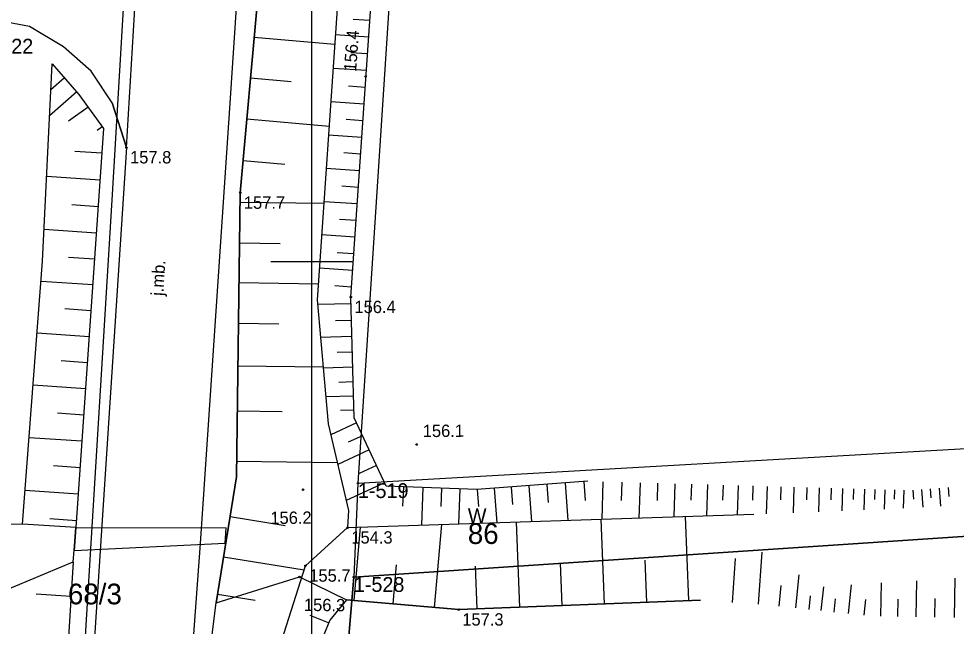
# Model space of a CAD drawing. Extents: x 5598798 to 5599616, y 5661498 to 5662453.
# Drawn here: x 5599182.2 to 5599239.2, y 5661877.8 to 5661914.8 of the extents above; entities that cross this region are included whole.
import ezdxf

# ---------------------------------------------------------------- set-up
doc = ezdxf.new("R2010")
doc.units = 0
for name, color, linetype in [('BUBZ_L_1', 7, 'Continuous'), ('BUIB_L_4', 7, 'Continuous'), ('Dzialki', 7, 'Continuous'), ('Kontury', 7, 'Continuous'), ('KTJZ_E_T_0', 7, 'Continuous'), ('KTJZ_L_0', 7, 'Continuous'), ('KTKR_L_0', 7, 'Continuous'), ('Numery_dzialek', 7, 'Continuous'), ('Numery_punktow', 7, 'Continuous'), ('Numery_uzytkow', 7, 'Continuous'), ('Podzial_sekcyjny_krzyze', 7, 'Continuous'), ('Podzial_sekcyjny_podstawowy', 7, 'Continuous'), ('PTRW_L_0', 7, 'Continuous'), ('PTRW_L_1', 7, 'Continuous'), ('Punkty', 7, 'Continuous'), ('RTPW_T_0', 7, 'Continuous'), ('SUPT_L_0', 7, 'Continuous'), ('Uzytki', 7, 'Continuous')]:
    doc.layers.add(name, color=color, linetype=linetype)

# ---------------------------------------------------------------- blocks, each defined once
blk = doc.blocks.new('GRO')
blk.add_circle((0, 0), 0.045)
blk = doc.blocks.new('POINT_DISPLAY')
blk.add_line((0, 0), (0, 0))
blk = doc.blocks.new('2_RTPW01')
blk.add_circle((0, 0), 0.045)

msp = doc.modelspace()

# ---------------------------------------------------------------- linework, layer by layer
at = {"layer": 'BUBZ_L_1'}
for p, q in [((5599195.64, 5661904.18), (5599197.66, 5661926.64)), ((5599201.55, 5661915.67), (5599200.33, 5661897.67)), ((5599202.37, 5661897.83), (5599203.6, 5661915.78)), ((5599203.522517, 5661914.649259), (5599202.506386, 5661914.718888)), ((5599196.491406, 5661913.646618), (5599201.383041, 5661913.206676)), ((5599203.452888, 5661913.633128), (5599201.42138, 5661913.772334)), ((5599203.383285, 5661912.617374), (5599202.367908, 5661912.686951)), ((5599183.618148, 5661900.022636), (5599184.202019, 5661912.021845)), ((5599184.202019, 5661912.021845), (5599185.830056, 5661910.15661)), ((5599203.313708, 5661911.601997), (5599201.283708, 5661911.7411)), ((5599184.951623, 5661911.163026), (5599184.125127, 5661910.441633)), ((5599196.268985, 5661911.173565), (5599198.742038, 5661910.951144)), ((5599185.701228, 5661910.304208), (5599184.048236, 5661908.861422)), ((5599185.830056, 5661910.15661), (5599187.322908, 5661908.083205)), ((5599203.244156, 5661910.586997), (5599202.229533, 5661910.656523)), ((5599203.174631, 5661909.572374), (5599201.146138, 5661909.711373)), ((5599186.381659, 5661909.390494), (5599185.185928, 5661908.529568)), ((5599196.044088, 5661908.672973), (5599201.045271, 5661908.223179)), ((5599203.105131, 5661908.558127), (5599202.091261, 5661908.627601)), ((5599187.322908, 5661908.083205), (5599185.646749, 5661883.824963)), ((5599187.242586, 5661908.194763), (5599186.933624, 5661907.97231)), ((5599203.035657, 5661907.544257), (5599201.008669, 5661907.683154)), ((5599187.219157, 5661906.581675), (5599185.58373, 5661906.694678)), ((5599195.816686, 5661906.144536), (5599198.345123, 5661905.917135)), ((5599202.966208, 5661906.530763), (5599201.953091, 5661906.600186)), ((5599202.896786, 5661905.517646), (5599200.871303, 5661905.65644)), ((5599187.106155, 5661904.946248), (5599183.868612, 5661905.16995)), ((5599202.827389, 5661904.504905), (5599201.815024, 5661904.574276)), ((5599195.41, 5661886.89), (5599195.64, 5661904.18)), ((5599186.994304, 5661903.327476), (5599185.392018, 5661903.438188)), ((5599195.632346, 5661903.604643), (5599200.727643, 5661903.536863)), ((5599202.758018, 5661903.492539), (5599200.734039, 5661903.63123)), ((5599202.688673, 5661902.48055), (5599201.677059, 5661902.549869)), ((5599186.883592, 5661901.725191), (5599183.711657, 5661901.94436)), ((5599202.619353, 5661901.468936), (5599200.596877, 5661901.607524)), ((5599195.599354, 5661901.124487), (5599198.07951, 5661901.091495)), ((5599202.55006, 5661900.457698), (5599201.539197, 5661900.526966)), ((5599182.39565, 5661884.02401), (5599183.618148, 5661900.022636)), ((5599186.774007, 5661900.139223), (5599185.204192, 5661900.247692)), ((5599202.480791, 5661899.446835), (5599200.459816, 5661899.58532)), ((5599186.665538, 5661898.569409), (5599183.523691, 5661898.786499)), ((5599195.567236, 5661898.710037), (5599200.396138, 5661898.6458)), ((5599202.411549, 5661898.436347), (5599201.401437, 5661898.505564)), ((5599200.33, 5661897.67), (5599201, 5661890.13)), ((5599202.57, 5661890.48), (5599202.37, 5661897.83)), ((5599186.556993, 5661896.998485), (5599184.980353, 5661897.107425)), ((5599202.381008, 5661897.425438), (5599200.356627, 5661897.370352)), ((5599202.408551, 5661896.413247), (5599201.427485, 5661896.386551)), ((5599195.534459, 5661896.24609), (5599197.998406, 5661896.213313)), ((5599186.448053, 5661895.421845), (5599183.283299, 5661895.640519)), ((5599202.435247, 5661895.43218), (5599200.53345, 5661895.380431)), ((5599202.461122, 5661894.481282), (5599201.539463, 5661894.456203)), ((5599186.338716, 5661893.839468), (5599184.750581, 5661893.949203)), ((5599195.499916, 5661893.649342), (5599200.693412, 5661893.580255)), ((5599202.486201, 5661893.559623), (5599200.699566, 5661893.511008)), ((5599186.228982, 5661892.251333), (5599183.041153, 5661892.471601)), ((5599202.510509, 5661892.666306), (5599201.644661, 5661892.642745)), ((5599202.534069, 5661891.800458), (5599200.855622, 5661891.754786)), ((5599186.118848, 5661890.657419), (5599184.519133, 5661890.767954)), ((5599195.463511, 5661890.912634), (5599198.200218, 5661890.876229)), ((5599202.556905, 5661890.961234), (5599201.743488, 5661890.939101)), ((5599202.710726, 5661890.178963), (5599201.156826, 5661889.452562)), ((5599204.51, 5661886.33), (5599202.57, 5661890.48)), ((5599201, 5661890.13), (5599202.22, 5661884.86)), ((5599186.008313, 5661889.057705), (5599182.797242, 5661889.279579)), ((5599203.073926, 5661889.402013), (5599202.214259, 5661889.000145)), ((5599203.475795, 5661888.542346), (5599201.573414, 5661887.65304)), ((5599185.897376, 5661887.45217), (5599184.285998, 5661887.56351)), ((5599195.422781, 5661887.850777), (5599201.546496, 5661887.769316)), ((5599203.920448, 5661887.591156), (5599202.86799, 5661887.099163)), ((5599194.18, 5661879.24), (5599195.41, 5661886.89)), ((5599204.41244, 5661886.538698), (5599202.083426, 5661885.449954)), ((5599210.04, 5661886.12), (5599204.51, 5661886.33)), ((5599205.564329, 5661886.289962), (5599205.519298, 5661885.104138)), ((5599206.750153, 5661886.244931), (5599206.66328, 5661883.957291)), ((5599207.893973, 5661886.201495), (5599207.852075, 5661885.098191)), ((5599208.997277, 5661886.159597), (5599208.91645, 5661884.03115)), ((5599216.78, 5661886.63), (5599210.04, 5661886.12)), ((5599211.085384, 5661886.199102), (5599211.243656, 5661884.107437)), ((5599212.131217, 5661886.278237), (5599212.212045, 5661885.210034)), ((5599213.199421, 5661886.359066), (5599213.364535, 5661884.17696)), ((5599214.290474, 5661886.441623), (5599214.374797, 5661885.327232)), ((5599215.404865, 5661886.525947), (5599215.577119, 5661884.249489)), ((5599216.543094, 5661886.612074), (5599216.631064, 5661885.449497)), ((5599217.707941, 5661886.603568), (5599217.642815, 5661884.317203)), ((5599218.851123, 5661886.571006), (5599218.819559, 5661885.462874)), ((5599219.959255, 5661886.539441), (5599219.898062, 5661884.39113)), ((5599221.033411, 5661886.508845), (5599221.003752, 5661885.467624)), ((5599222.074632, 5661886.479186), (5599222.017134, 5661884.460594)), ((5599223.083928, 5661886.450437), (5599223.05606, 5661885.472087)), ((5599224.062278, 5661886.42257), (5599224.008252, 5661884.525863)), ((5599225.010631, 5661886.395557), (5599224.984447, 5661885.476281)), ((5599225.929907, 5661886.369372), (5599225.879143, 5661884.587192)), ((5599226.820997, 5661886.34399), (5599226.796394, 5661885.480221)), ((5599227.684766, 5661886.319386), (5599227.637234, 5661884.650657)), ((5599228.51913, 5661886.29562), (5599228.496185, 5661885.490062)), ((5599229.324689, 5661886.272674), (5599229.280382, 5661884.717181)), ((5599230.102435, 5661886.250521), (5599230.081046, 5661885.499626)), ((5599230.85333, 5661886.229132), (5599230.812029, 5661884.779191)), ((5599231.5783, 5661886.208482), (5599231.558363, 5661885.508541)), ((5599232.278241, 5661886.188545), (5599232.239743, 5661884.836994)), ((5599232.954016, 5661886.169296), (5599232.935432, 5661885.516851)), ((5599233.606461, 5661886.150711), (5599233.570575, 5661884.890873)), ((5599237.615384, 5661886.162655), (5599237.658168, 5661885.619911)), ((5599238.158128, 5661886.20544), (5599238.244467, 5661885.110186)), ((5599238.705755, 5661886.248609), (5599238.749313, 5661885.696056)), ((5599185.786036, 5661885.840792), (5599182.551553, 5661886.064283)), ((5599210.061454, 5661886.121623), (5599210.138933, 5661885.097693)), ((5599234.23638, 5661886.132768), (5599234.219056, 5661885.524597)), ((5599234.844551, 5661886.115445), (5599234.8111, 5661884.941097)), ((5599235.431725, 5661886.09872), (5599235.415577, 5661885.531818)), ((5599235.998626, 5661886.082572), (5599235.967446, 5661884.987913)), ((5599236.545671, 5661886.07833), (5599236.587594, 5661885.546524)), ((5599237.077478, 5661886.120252), (5599237.162284, 5661885.04444)), ((5599195.023599, 5661884.486771), (5599198.375505, 5661883.947837)), ((5599202.22, 5661884.86), (5599202.17, 5661883.81)), ((5599202.17, 5661883.81), (5599226.88, 5661884.62)), ((5599222.921658, 5661879.372052), (5599222.719977, 5661884.483633)), ((5599185.646749, 5661883.824963), (5599182.39565, 5661884.02401)), ((5599185.67429, 5661884.22355), (5599184.051164, 5661884.335703)), ((5599207.462869, 5661878.946736), (5599207.899199, 5661883.997804)), ((5599212.647264, 5661878.966668), (5599212.44288, 5661884.146747)), ((5599217.801557, 5661879.170034), (5599217.598529, 5661884.315751)), ((5599199.61, 5661881.49), (5599202.17, 5661883.81)), ((5599202.562704, 5661879.37003), (5599202.948449, 5661883.835518)), ((5599227.169305, 5661879.151962), (5599227.39118, 5661882.317959)), ((5599181.124984, 5661879.908151), (5599185.479134, 5661881.732747)), ((5599185.479134, 5661881.732747), (5599182.923041, 5661841.717691)), ((5599194.629438, 5661882.035288), (5599199.532405, 5661881.246968)), ((5599215.228699, 5661879.06852), (5599215.126846, 5661881.649955)), ((5599220.365868, 5661879.271211), (5599220.264691, 5661881.835521)), ((5599225.586306, 5661879.2629), (5599225.772964, 5661881.926365)), ((5599198.02, 5661876.51), (5599199.61, 5661881.49)), ((5599204.937335, 5661879.164901), (5599205.142464, 5661881.539532)), ((5599210.057224, 5661878.864476), (5599209.954691, 5661881.463149)), ((5599229.434035, 5661878.92122), (5599229.645525, 5661880.945479)), ((5599234.601569, 5661878.428875), (5599234.641444, 5661880.441587)), ((5599236.748534, 5661878.38634), (5599236.79198, 5661880.579344)), ((5599239.087815, 5661878.339996), (5599239.135153, 5661880.72944)), ((5599228.421906, 5661879.026965), (5599228.552722, 5661880.279059)), ((5599230.980807, 5661878.759617), (5599231.133055, 5661880.21685)), ((5599232.646927, 5661878.585545), (5599232.828711, 5661880.325469)), ((5599185.344339, 5661879.622558), (5599183.234126, 5661879.757355)), ((5599194.262906, 5661879.755638), (5599196.542557, 5661879.389106)), ((5599202.1, 5661879.41), (5599201.09, 5661878.18)), ((5599208.93, 5661878.82), (5599202.1, 5661879.41)), ((5599223.63, 5661879.4), (5599208.93, 5661878.82)), ((5599230.25219, 5661878.835741), (5599230.337669, 5661879.653896)), ((5599231.776965, 5661878.676436), (5599231.860146, 5661879.472595)), ((5599233.597534, 5661878.486228), (5599233.696851, 5661879.436835)), ((5599235.652032, 5661878.408064), (5599235.672843, 5661879.458526)), ((5599237.893092, 5661878.363665), (5599237.915768, 5661879.508224)), ((5599192.07, 5661862.5), (5599194.18, 5661879.24)), ((5599201.09, 5661878.18), (5599199.56, 5661874.43)), ((5599201.020079, 5661878.008624), (5599199.904587, 5661878.463744))]:
    msp.add_line(p, q, dxfattribs=at)
at = {"layer": 'BUIB_L_4'}
for p, q in [((5599185.646749, 5661883.824963), (5599185.534757, 5661882.427047)), ((5599185.646749, 5661883.824963), (5599194.779859, 5661883.794812)), ((5599194.727097, 5661882.855368), (5599194.779859, 5661883.794812)), ((5599185.534757, 5661882.427047), (5599194.727097, 5661882.855368))]:
    msp.add_line(p, q, dxfattribs=at)
at = {"layer": 'Dzialki'}
for p, q in [((5599207.13, 5661952.92), (5599202.8, 5661886.51)), ((5599202.8, 5661886.51), (5599366.78, 5661895.9)), ((5599202.55, 5661880.8), (5599363.22, 5661891.49)), ((5599202.8, 5661886.51), (5599202.55, 5661880.8)), ((5599202.55, 5661880.8), (5599192.37, 5661761.69))]:
    msp.add_line(p, q, dxfattribs=at)
at = {"layer": 'Kontury'}
for p, q in [((5599207.13, 5661952.92), (5599202.8, 5661886.51)), ((5599202.55, 5661880.8), (5599363.22, 5661891.49)), ((5599202.8, 5661886.51), (5599202.55, 5661880.8)), ((5599192.37, 5661761.69), (5599202.55, 5661880.8))]:
    msp.add_line(p, q, dxfattribs=at)
at = {"layer": 'KTJZ_L_0'}
for p, q in [((5599196.72, 5661936.01), (5599194.99, 5661909.33)), ((5599195.64, 5661904.18), (5599197.66, 5661926.64)), ((5599188.72, 5661906.93), (5599189.38, 5661917.79)), ((5599182.82, 5661914.28), (5599180.59, 5661914.71)), ((5599184.89, 5661913.05), (5599182.82, 5661914.28)), ((5599186.58, 5661911.58), (5599184.89, 5661913.05)), ((5599187.86, 5661909.64), (5599186.58, 5661911.58)), ((5599187.86, 5661909.64), (5599188.72, 5661906.93)), ((5599194.99, 5661909.33), (5599193.21, 5661882.85)), ((5599188.72, 5661906.93), (5599185.78, 5661861.81)), ((5599195.41, 5661886.89), (5599195.64, 5661904.18)), ((5599194.18, 5661879.24), (5599195.41, 5661886.89)), ((5599193.21, 5661882.85), (5599191.03, 5661853.22)), ((5599192.07, 5661862.5), (5599194.18, 5661879.24))]:
    msp.add_line(p, q, dxfattribs=at)
at = {"layer": 'KTKR_L_0'}
for p, q in [((5599182.82, 5661914.28), (5599180.59, 5661914.71)), ((5599184.89, 5661913.05), (5599182.82, 5661914.28)), ((5599186.58, 5661911.58), (5599184.89, 5661913.05)), ((5599187.86, 5661909.64), (5599186.58, 5661911.58)), ((5599188.72, 5661906.93), (5599187.86, 5661909.64))]:
    msp.add_line(p, q, dxfattribs=at)
at = {"layer": 'Podzial_sekcyjny_krzyze'}
for p, q in [((5599200, 5661897.5), (5599200, 5661902.5)), ((5599197.5, 5661900), (5599202.5, 5661900))]:
    msp.add_line(p, q, dxfattribs=at)
at = {"layer": 'Podzial_sekcyjny_podstawowy'}
msp.add_line((5599200, 5661750), (5599200, 5662000), dxfattribs=at)
at = {"layer": 'PTRW_L_0'}
for p, q in [((5599197.66, 5661926.64), (5599195.64, 5661904.18)), ((5599202.37, 5661897.83), (5599203.6, 5661915.78)), ((5599195.64, 5661904.18), (5599195.41, 5661886.89)), ((5599202.57, 5661890.48), (5599202.37, 5661897.83)), ((5599204.51, 5661886.33), (5599202.57, 5661890.48)), ((5599195.41, 5661886.89), (5599194.18, 5661879.24)), ((5599210.04, 5661886.12), (5599204.51, 5661886.33)), ((5599216.78, 5661886.63), (5599210.04, 5661886.12)), ((5599194.18, 5661879.24), (5599199.25, 5661880.81)), ((5599199.25, 5661880.81), (5599202.1, 5661879.41)), ((5599202.1, 5661879.41), (5599208.93, 5661878.82)), ((5599208.93, 5661878.82), (5599223.63, 5661879.4))]:
    msp.add_line(p, q, dxfattribs=at)
at = {"layer": 'PTRW_L_1'}
for p, q in [((5599182.39565, 5661884.02401), (5599181.499939, 5661883.990835)), ((5599185.646749, 5661883.824963), (5599182.39565, 5661884.02401)), ((5599185.534757, 5661882.427047), (5599185.646749, 5661883.824963)), ((5599185.479134, 5661881.732747), (5599185.534757, 5661882.427047)), ((5599181.124984, 5661879.908151), (5599185.479134, 5661881.732747))]:
    msp.add_line(p, q, dxfattribs=at)
at = {"layer": 'SUPT_L_0'}
for p, q in [((5599189.54249, 5661932.273767), (5599187.842687, 5661904.061861)), ((5599187.842687, 5661904.061861), (5599186.246732, 5661877.883274)), ((5599186.246732, 5661877.883274), (5599183.629748, 5661836.324248))]:
    msp.add_line(p, q, dxfattribs=at)
at = {"layer": 'Uzytki'}
for p, q in [((5599207.13, 5661952.92), (5599202.8, 5661886.51)), ((5599202.8, 5661886.51), (5599366.78, 5661895.9)), ((5599363.22, 5661891.49), (5599202.55, 5661880.8)), ((5599202.8, 5661886.51), (5599202.55, 5661880.8)), ((5599202.55, 5661880.8), (5599192.37, 5661761.69))]:
    msp.add_line(p, q, dxfattribs=at)

# ---------------------------------------------------------------- block references
at = {"layer": 'BUBZ_L_1'}
for p in [(5599184.202019, 5661912.021845), (5599185.479134, 5661881.732747)]:
    msp.add_blockref('POINT_DISPLAY', p, dxfattribs=at)
at = {"layer": 'Punkty'}
for p in [(5599202.8, 5661886.51), (5599202.55, 5661880.8)]:
    msp.add_blockref('GRO', p, dxfattribs=at)
at = {"layer": 'RTPW_T_0'}
for p in [(5599203.266683, 5661911.245645), (5599206.366622, 5661888.865526), (5599199.465831, 5661886.117461), (5599199.246317, 5661880.809974)]:
    msp.add_blockref('2_RTPW01', p, dxfattribs=at)
at = {"layer": 'RTPW_T_0', "rotation": -3.0000000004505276e-06}
for p in [(5599188.72, 5661906.93), (5599195.64, 5661904.18), (5599202.37, 5661897.83), (5599202.17, 5661883.81), (5599199.61, 5661881.49), (5599208.93, 5661878.82)]:
    msp.add_blockref('2_RTPW01', p, dxfattribs=at)

# ---------------------------------------------------------------- texts
at = {"layer": 'KTJZ_E_T_0'}
msp.add_text('j.mb.', height=0.75, rotation=86.399998, dxfattribs=at).set_placement((5599190.954998, 5661897.888391))
at = {"layer": 'Numery_dzialek'}
for s, p in [('86', (5599209.48674, 5661882.816092)), ('68/3', (5599185.160937, 5661879.142776))]:
    msp.add_text(s, height=1.26, dxfattribs=at).set_placement(p)
at = {"layer": 'Numery_punktow'}
for s, p in [('1-22', (5599180.64, 5661912.64)), ('1-519', (5599202.8, 5661885.61)), ('1-528', (5599202.55, 5661879.9))]:
    msp.add_text(s, height=0.9, dxfattribs=at).set_placement(p)
at = {"layer": 'Numery_uzytkow'}
msp.add_text('W', height=0.9, dxfattribs=at).set_placement((5599209.48674, 5661884.076092))
at = {"layer": 'RTPW_T_0'}
for s, rotation, p in [('156.4', 85.869156, (5599202.690444, 5661911.530597)), ('156.1', 0.496053, (5599206.746257, 5661889.311171)), ('156.2', 0.35699, (5599197.47605, 5661884.02871)), ('156.3', 359.489356, (5599199.514107, 5661878.740631))]:
    msp.add_text(s, height=0.75, rotation=rotation, dxfattribs=at).set_placement(p)
for s, p in [('157.8', (5599188.94, 5661905.96)), ('157.7', (5599195.86, 5661903.2)), ('156.4', (5599202.59, 5661896.86)), ('154.3', (5599202.4, 5661882.84)), ('155.7', (5599199.84, 5661880.52)), ('157.3', (5599209.15, 5661877.85))]:
    msp.add_text(s, height=0.75, dxfattribs=at).set_placement(p)

doc.saveas('drawing.dxf')
